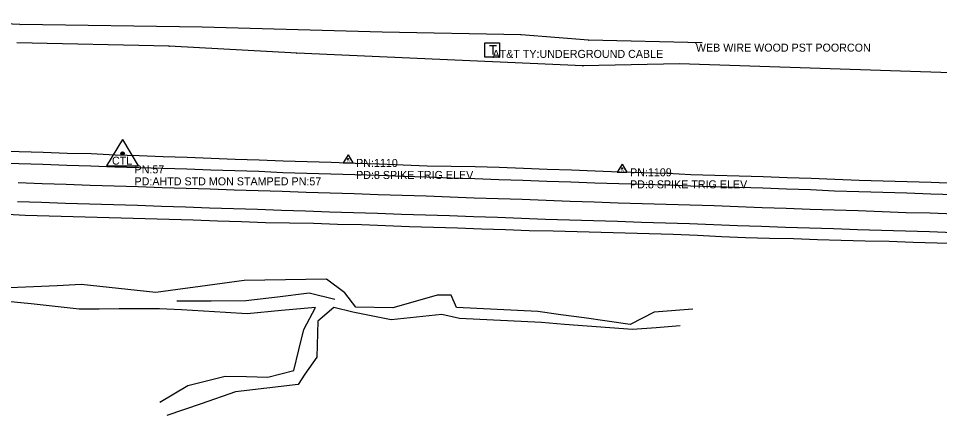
# Model space of a CAD drawing. Extents: x 976456 to 985170, y 1525951 to 1527080.
# Drawn here: x 978656 to 979231, y 1526329 to 1526577 of the extents above; entities that cross this region are included whole.
import ezdxf

# ---------------------------------------------------------------- set-up
doc = ezdxf.new("R2010")
doc.units = 0
for name, color, linetype in [('S_DITCHLINE', 7, 'Continuous'), ('S_EDGE_PAVEMENT', 7, 'Continuous'), ('S_FENCE', 7, 'Continuous'), ('S_FIBER_OPTIC_CABLE', 7, 'Continuous'), ('S_MSC_PT_SYM', 7, 'Continuous'), ('S_PAVEMENT_CROWN', 7, 'Continuous'), ('S_PRIMARY_CTL', 7, 'Continuous'), ('S_PRIMARY_CTL_ANNOT', 7, 'Continuous'), ('S_SECONDARY_CTL', 7, 'Continuous'), ('S_SECONDARY_CTL_ANNOT', 7, 'Continuous'), ('S_SHOULDER', 7, 'Continuous'), ('S_SURVEY_TEXT_ANNOT', 7, 'Continuous'), ('S_TELEPHONE_UTILITIES', 7, 'Continuous'), ('S_TELEPHONE_UTILITIES_ANNOT', 7, 'Continuous'), ('S_UTL_PT_SYM', 7, 'Continuous')]:
    doc.layers.add(name, color=color, linetype=linetype)

msp = doc.modelspace()

# ---------------------------------------------------------------- linework, layer by layer
at = {"layer": 'S_DITCHLINE'}
for points in [[(979077.19, 1526395.41), (979052.87, 1526393.57), (979037.98, 1526385.83), (979023.55, 1526387.84), (979009.13, 1526389.85), (978994.7, 1526391.86), (978980.28, 1526393.87), (978967.59, 1526394.49), (978954.9, 1526395.11), (978942.21, 1526395.74), (978929.52, 1526396.36), (978926.07, 1526404.18), (978917.42, 1526404.1), (978903.57, 1526400.11), (978889.71, 1526396.12), (978866.52, 1526396.56), (978859.77, 1526405.46), (978848.29, 1526414.18), (978835.45, 1526413.98), (978822.61, 1526413.77), (978809.78, 1526413.57), (978796.94, 1526413.36), (978783.12, 1526411.46), (978769.3, 1526409.55), (978755.48, 1526407.65), (978741.66, 1526405.75), (978718.32, 1526408.21), (978694.98, 1526410.68), (978680.08, 1526410.03), (978665.19, 1526409.37), (978650.29, 1526408.71)], [(978853.5, 1526401.36), (978837.35, 1526405.28), (978817.59, 1526402.88), (978797.82, 1526400.48), (978776.28, 1526400.37), (978754.74, 1526400.27)], [(978744.09, 1526337.24), (978761.76, 1526347.61), (978785.02, 1526353.48), (978798.29, 1526353.2), (978811.56, 1526352.93), (978827.81, 1526357.02), (978830.93, 1526369.87), (978834.05, 1526382.73), (978841.34, 1526396.42), (978820.07, 1526394.45), (978798.79, 1526392.48), (978785.09, 1526393.27), (978771.4, 1526394.06), (978757.7, 1526394.85), (978744, 1526395.64), (978731.43, 1526395.57), (978718.86, 1526395.49), (978706.3, 1526395.42), (978693.73, 1526395.35), (978678.72, 1526396.96), (978663.72, 1526398.58), (978648.71, 1526400.19)], [(979069.12, 1526384.92), (979054.26, 1526383.73), (979039.41, 1526382.54), (979025.22, 1526383.65), (979011.03, 1526384.76), (978996.85, 1526385.87), (978982.66, 1526386.98), (978969.83, 1526387.6), (978957, 1526388.22), (978944.16, 1526388.83), (978931.33, 1526389.45), (978920.39, 1526392.09), (978904.51, 1526390.37), (978888.62, 1526388.65), (978864.8, 1526393.56), (978852.79, 1526396.4), (978842.83, 1526387.86), (978842.24, 1526365.34), (978834.8, 1526354.76), (978830.68, 1526348.33), (978811.07, 1526345.96), (978791.45, 1526343.58), (978770.01, 1526336.21), (978748.58, 1526328.83)]]:
    msp.add_lwpolyline(points, dxfattribs=at)
at = {"layer": 'S_EDGE_PAVEMENT'}
for points in [[(978641.1, 1526486.88), (978656.09, 1526486.41), (978671.08, 1526485.88), (978686, 1526485.37), (978701, 1526484.89), (978715.99, 1526484.41), (978715.99, 1526484.41), (978730.98, 1526483.94), (978745.97, 1526483.46), (978760.97, 1526482.98), (978775.96, 1526482.5), (978790.95, 1526482.03), (978805.94, 1526481.56), (978820.92, 1526480.87), (978835.92, 1526480.4), (978850.91, 1526479.93), (978865.9, 1526479.48), (978880.87, 1526479.02), (978895.86, 1526478.47), (978910.85, 1526478.03), (978925.84, 1526477.43), (978940.84, 1526476.99), (978955.83, 1526476.35), (978955.83, 1526476.35), (978970.94, 1526475.89), (978985.93, 1526475.36), (979000.93, 1526474.99), (979015.91, 1526474.4), (979030.91, 1526473.96), (979045.9, 1526473.56), (979060.9, 1526473.04), (979075.75, 1526472.44), (979075.75, 1526472.44), (979090.74, 1526471.95), (979105.74, 1526471.56), (979120.73, 1526471.12), (979135.72, 1526470.53), (979150.71, 1526470.1), (979165.7, 1526469.4), (979180.81, 1526468.8), (979195.8, 1526468.49), (979210.8, 1526468.02), (979210.8, 1526468.02), (979225.79, 1526467.52), (979240.78, 1526466.95)], [(978655.21, 1526462.69), (978670.21, 1526462.19), (978685.25, 1526461.69), (978685.25, 1526461.69), (978700.24, 1526461.21), (978715.23, 1526460.73), (978730.23, 1526460.28), (978730.23, 1526460.28), (978745.22, 1526459.82), (978745.22, 1526459.82), (978760.21, 1526459.3), (978775.2, 1526458.73), (978775.2, 1526458.73), (978790.2, 1526458.23), (978805.19, 1526457.76), (978820.18, 1526457.26), (978835.18, 1526456.77), (978850.17, 1526456.28), (978865.16, 1526455.79), (978865.16, 1526455.79), (978880.17, 1526455.3), (978895.16, 1526454.77), (978910.15, 1526454.3), (978925.15, 1526453.79), (978925.15, 1526453.79), (978940.14, 1526453.28), (978955.13, 1526452.75), (978970.01, 1526452.21), (978985.01, 1526451.69), (978985.01, 1526451.69), (979000, 1526451.21), (979014.99, 1526450.74), (979029.98, 1526450.25), (979029.98, 1526450.25), (979044.97, 1526449.68), (979059.97, 1526449.26), (979059.97, 1526449.26), (979075.07, 1526448.84), (979090.06, 1526448.27), (979090.06, 1526448.27), (979105.05, 1526447.69), (979120.04, 1526447.22), (979135.03, 1526446.68), (979150.02, 1526446.19), (979165.02, 1526445.72), (979165.02, 1526445.72), (979179.91, 1526445.18), (979194.9, 1526444.73), (979209.89, 1526444.29), (979224.89, 1526443.83), (979239.88, 1526443.35)]]:
    msp.add_lwpolyline(points, dxfattribs=at)
at = {"layer": 'S_FENCE'}
for p, q in [((978656.79, 1526573.29), (978581.16, 1526577.07)), ((978770.61, 1526571.57), (978656.79, 1526573.29)), ((978883.04, 1526568.43), (978770.61, 1526571.57)), ((978969.92, 1526566.74), (978883.04, 1526568.43)), ((979011.84, 1526563.43), (978969.92, 1526566.74)), ((979082.99, 1526561.79), (979011.84, 1526563.43))]:
    msp.add_line(p, q, dxfattribs=at)
at = {"layer": 'S_FIBER_OPTIC_CABLE'}
for p, q in [((978750.07, 1526559.66), (978654.88, 1526561.71)), ((978829.69, 1526555.3), (978750.07, 1526559.66)), ((979008.47, 1526547.36), (978829.69, 1526555.3)), ((979068.74, 1526548.75), (979008.47, 1526547.36)), ((982227.16, 1526444.43), (979068.74, 1526548.75))]:
    msp.add_line(p, q, dxfattribs=at)
at = {"layer": 'S_MSC_PT_SYM'}
for points in [[(978656.79, 1526573.29), (978656.79, 1526573.34), (978656.79, 1526573.29), (978656.74, 1526573.29), (978656.79, 1526573.29), (978656.79, 1526573.24), (978656.79, 1526573.29), (978656.84, 1526573.29)], [(978770.61, 1526571.57), (978770.61, 1526571.62), (978770.61, 1526571.57), (978770.56, 1526571.57), (978770.61, 1526571.57), (978770.61, 1526571.52), (978770.61, 1526571.57), (978770.66, 1526571.57)], [(978883.04, 1526568.43), (978883.04, 1526568.48), (978883.04, 1526568.43), (978882.99, 1526568.43), (978883.04, 1526568.43), (978883.04, 1526568.38), (978883.04, 1526568.43), (978883.09, 1526568.43)], [(978969.92, 1526566.74), (978969.92, 1526566.79), (978969.92, 1526566.74), (978969.87, 1526566.74), (978969.92, 1526566.74), (978969.92, 1526566.69), (978969.92, 1526566.74), (978969.97, 1526566.74)], [(979011.84, 1526563.43), (979011.84, 1526563.48), (979011.84, 1526563.43), (979011.79, 1526563.43), (979011.84, 1526563.43), (979011.84, 1526563.38), (979011.84, 1526563.43), (979011.89, 1526563.43)], [(979079.01, 1526561.31), (979079.01, 1526561.36), (979079.01, 1526561.31), (979078.96, 1526561.31), (979079.01, 1526561.31), (979079.01, 1526561.26), (979079.01, 1526561.31), (979079.06, 1526561.31)], [(979082.99, 1526561.79), (979082.99, 1526561.84), (979082.99, 1526561.79), (979082.94, 1526561.79), (979082.99, 1526561.79), (979082.99, 1526561.74), (979082.99, 1526561.79), (979083.04, 1526561.79)]]:
    msp.add_lwpolyline(points, dxfattribs=at)
at = {"layer": 'S_PAVEMENT_CROWN'}
msp.add_lwpolyline([(978655.65, 1526474.42), (978670.64, 1526473.94), (978670.64, 1526473.94), (978685.62, 1526473.42), (978700.62, 1526472.95), (978700.62, 1526472.95), (978715.61, 1526472.43), (978715.61, 1526472.43), (978730.6, 1526471.96), (978730.6, 1526471.96), (978745.59, 1526471.42), (978745.59, 1526471.42), (978760.58, 1526470.95), (978760.58, 1526470.95), (978775.58, 1526470.47), (978775.58, 1526470.47), (978790.57, 1526470), (978790.57, 1526470), (978805.56, 1526469.53), (978805.56, 1526469.53), (978820.55, 1526469.02), (978820.55, 1526469.02), (978835.55, 1526468.54), (978850.54, 1526468.07), (978850.54, 1526468.07), (978865.53, 1526467.56), (978880.52, 1526467.1), (978895.51, 1526466.66), (978895.51, 1526466.66), (978910.5, 1526466.13), (978910.5, 1526466.13), (978925.49, 1526465.52), (978925.49, 1526465.52), (978940.48, 1526465.02), (978955.48, 1526464.57), (978955.48, 1526464.57), (978970.48, 1526464.07), (978985.47, 1526463.52), (979000.46, 1526462.93), (979015.45, 1526462.4), (979015.45, 1526462.4), (979030.44, 1526461.9), (979030.44, 1526461.9), (979045.43, 1526461.46), (979045.43, 1526461.46), (979060.43, 1526461.06), (979060.43, 1526461.06), (979075.41, 1526460.55), (979090.4, 1526460.12), (979090.4, 1526460.12), (979105.39, 1526459.45), (979105.39, 1526459.45), (979120.38, 1526458.86), (979120.38, 1526458.86), (979135.37, 1526458.43), (979135.37, 1526458.43), (979150.36, 1526457.9), (979150.36, 1526457.9), (979165.35, 1526457.47), (979165.35, 1526457.47), (979180.36, 1526457.01), (979180.36, 1526457.01), (979195.34, 1526456.44), (979210.33, 1526455.87), (979210.33, 1526455.87), (979225.33, 1526455.53), (979225.33, 1526455.53), (979240.32, 1526454.96)], dxfattribs=at)
at = {"layer": 'S_PRIMARY_CTL'}
for p, q in [((978720.86, 1526501.44), (978710.83, 1526484.93)), ((978720.86, 1526501.44), (978730.68, 1526484.93)), ((978710.83, 1526484.93), (978730.68, 1526484.93))]:
    msp.add_line(p, q, dxfattribs=at)
for radius in [1.04, 0.609, 0.344]:
    msp.add_circle((978720.86, 1526492.74), radius, dxfattribs=at)
at = {"layer": 'S_SECONDARY_CTL'}
for p, q in [((978861.76, 1526491.85), (978858.75, 1526486.9)), ((978861.76, 1526491.85), (978864.7, 1526486.9)), ((978858.75, 1526486.9), (978864.7, 1526486.9)), ((979032.88, 1526485.99), (979029.87, 1526481.03)), ((979032.88, 1526485.99), (979035.82, 1526481.03)), ((979029.87, 1526481.03), (979035.82, 1526481.03))]:
    msp.add_line(p, q, dxfattribs=at)
for centre, radius in [((978861.76, 1526489.24), 0.311), ((978861.76, 1526489.24), 0.183), ((978861.76, 1526489.24), 0.103), ((979032.88, 1526483.38), 0.311), ((979032.88, 1526483.38), 0.183), ((979032.88, 1526483.38), 0.103)]:
    msp.add_circle(centre, radius, dxfattribs=at)
at = {"layer": 'S_SHOULDER'}
for points in [[(978641.38, 1526494.37), (978656.37, 1526493.9), (978671.36, 1526493.38), (978686.25, 1526492.94), (978701.25, 1526492.55), (978716.23, 1526491.9), (978731.23, 1526491.42), (978746.21, 1526490.73), (978761.21, 1526490.26), (978776.2, 1526489.78), (978791.17, 1526489.09), (978806.17, 1526488.62), (978821.16, 1526488.12), (978836.15, 1526487.62), (978851.14, 1526487.15), (978866.14, 1526486.68), (978881.09, 1526486.22), (978896.08, 1526485.64), (978911.06, 1526484.84), (978926.06, 1526484.71), (978941.06, 1526484.45), (978956.06, 1526484.1), (978971.24, 1526483.5), (978986.22, 1526482.88), (979001.22, 1526482.43), (979016.2, 1526481.74), (979031.2, 1526481.23), (979046.19, 1526480.83), (979061.18, 1526480.27), (979075.96, 1526479.58), (979090.95, 1526479.13), (979105.95, 1526478.74), (979120.94, 1526478.28), (979135.93, 1526477.69), (979150.93, 1526477.26), (979165.91, 1526476.56), (979181.08, 1526475.98), (979196.08, 1526475.66), (979211.07, 1526475.16), (979226.07, 1526474.76), (979241.06, 1526474.19)], [(978645.05, 1526454.87), (978660.04, 1526454.15), (978675.03, 1526453.72), (978690.12, 1526453.22), (978705.12, 1526452.89), (978720.11, 1526452.42), (978735.1, 1526452.02), (978750.1, 1526451.55), (978765.09, 1526451.09), (978780.09, 1526450.53), (978795.08, 1526450.08), (978810.08, 1526449.61), (978825.08, 1526449.38), (978840.07, 1526449), (978855.06, 1526448.49), (978870.06, 1526448.2), (978885.08, 1526447.62), (978900.07, 1526447.09), (978915.06, 1526446.62), (978930.05, 1526446.08), (978945.05, 1526445.58), (978960.04, 1526445.04), (978974.85, 1526444.6), (978989.85, 1526444.24), (979004.85, 1526443.96), (979019.85, 1526443.53), (979034.84, 1526443.03), (979049.84, 1526442.64), (979064.83, 1526442.17), (979079.99, 1526441.55), (979094.98, 1526440.73), (979109.97, 1526440.18), (979124.96, 1526439.77), (979139.96, 1526439.52), (979154.95, 1526438.85), (979169.78, 1526438.49), (979184.77, 1526438.13), (979199.77, 1526437.75), (979214.76, 1526437.29), (979229.76, 1526436.84), (979244.75, 1526436.44)]]:
    msp.add_lwpolyline(points, dxfattribs=at)
at = {"layer": 'S_TELEPHONE_UTILITIES'}
msp.add_lwpolyline([(978947.24, 1526552.87), (978947.24, 1526561.87), (978956.24, 1526561.87), (978956.24, 1526552.87)], close=True, dxfattribs=at)
at = {"layer": 'S_UTL_PT_SYM'}
for points in [[(978750.07, 1526559.66), (978750.07, 1526559.71), (978750.07, 1526559.66), (978750.02, 1526559.66), (978750.07, 1526559.66), (978750.07, 1526559.61), (978750.07, 1526559.66), (978750.12, 1526559.66)], [(978829.69, 1526555.3), (978829.69, 1526555.35), (978829.69, 1526555.3), (978829.64, 1526555.3), (978829.69, 1526555.3), (978829.69, 1526555.25), (978829.69, 1526555.3), (978829.74, 1526555.3)], [(979008.47, 1526547.36), (979008.47, 1526547.41), (979008.47, 1526547.36), (979008.42, 1526547.36), (979008.47, 1526547.36), (979008.47, 1526547.31), (979008.47, 1526547.36), (979008.52, 1526547.36)], [(979068.74, 1526548.75), (979068.74, 1526548.8), (979068.74, 1526548.75), (979068.69, 1526548.75), (979068.74, 1526548.75), (979068.74, 1526548.7), (979068.74, 1526548.75), (979068.79, 1526548.75)]]:
    msp.add_lwpolyline(points, dxfattribs=at)

# ---------------------------------------------------------------- texts
at = {"layer": 'S_PRIMARY_CTL'}
msp.add_text('CTL', height=5, rotation=360, dxfattribs=at).set_placement((978714.27, 1526485.67))
at = {"layer": 'S_PRIMARY_CTL_ANNOT'}
for s, p in [('PN:57', (978728.36, 1526480.24)), ('PD:AHTD STD MON STAMPED PN:57', (978728.36, 1526472.74))]:
    msp.add_text(s, height=5, dxfattribs=at).set_placement(p)
at = {"layer": 'S_SECONDARY_CTL'}
for p in [(978860.55, 1526487.23), (979031.67, 1526481.37)]:
    msp.add_text('TV', height=1.5, rotation=360, dxfattribs=at).set_placement(p)
at = {"layer": 'S_SECONDARY_CTL_ANNOT'}
for s, p in [('PN:1110', (978866.76, 1526484.24)), ('PN:1109', (979037.88, 1526478.38)), ('PD:8 SPIKE TRIG ELEV', (978866.76, 1526476.74)), ('PD:8 SPIKE TRIG ELEV', (979037.88, 1526470.88))]:
    msp.add_text(s, height=5, dxfattribs=at).set_placement(p)
at = {"layer": 'S_SURVEY_TEXT_ANNOT'}
msp.add_text('WEB WIRE WOOD PST POORCON', height=5, dxfattribs=at).set_placement((979079.01, 1526556.31))
at = {"layer": 'S_TELEPHONE_UTILITIES'}
msp.add_text('T', height=6, rotation=360, dxfattribs=at).set_placement((978949.8, 1526554.37))
at = {"layer": 'S_TELEPHONE_UTILITIES_ANNOT'}
msp.add_text('AT&T TY:UNDERGROUND CABLE', height=5, dxfattribs=at).set_placement((978951.97, 1526552.39))

doc.saveas('drawing.dxf')
